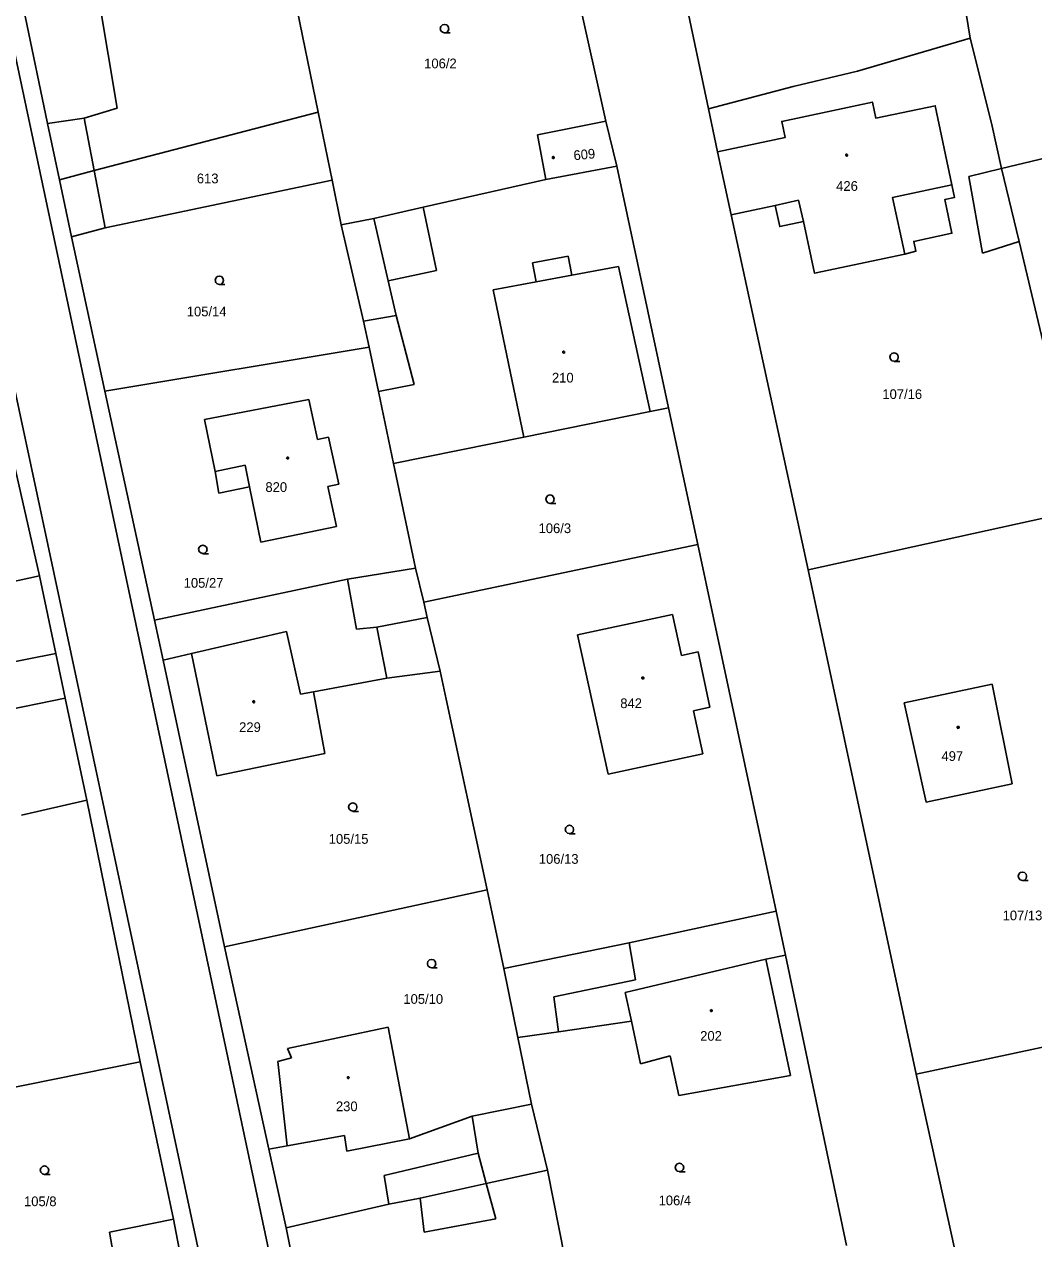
# Model space of a CAD drawing. Extents: x -757994 to -755874, y -1047691 to -1046119.
# Drawn here: x -756698 to -756609.7, y -1047019.3 to -1046913.1 of the extents above; entities that cross this region are included whole.
import ezdxf

# ---------------------------------------------------------------- set-up
doc = ezdxf.new("R2010")
doc.units = 0
doc.layers.add('katastrální mapa', color=7, linetype='Continuous')

msp = doc.modelspace()

# ---------------------------------------------------------------- linework, layer by layer
at = {"layer": 'katastrální mapa'}
for p, q in [((-756646.95, -1046878.79), (-756638.18, -1046920.5)), ((-756653.57, -1046892.67), (-756647.16, -1046921.56)), ((-756701.95, -1046901.14), (-756668.39, -1047059.3)), ((-756707.71, -1046903.74), (-756665.23, -1047102.74)), ((-756675.68, -1046904.52), (-756672.34, -1046920.77)), ((-756689.92, -1046920.42), (-756691.5, -1046911.04)), ((-756615.84, -1046910.85), (-756615.3, -1046914.3)), ((-756697.97, -1046912.37), (-756696.02, -1046921.77)), ((-756615.3, -1046914.3), (-756625.14, -1046917.2)), ((-756613.43, -1046921.73), (-756615.3, -1046914.3)), ((-756625.14, -1046917.2), (-756630.78, -1046918.54)), ((-756630.78, -1046918.54), (-756638.18, -1046920.5)), ((-756692.82, -1046921.29), (-756689.92, -1046920.42)), ((-756691.94, -1046925.89), (-756672.34, -1046920.77)), ((-756672.34, -1046920.77), (-756671.12, -1046926.73)), ((-756638.18, -1046920.5), (-756637.39, -1046924.25)), ((-756591.53, -1046920.69), (-756612.56, -1046925.71)), ((-756692.82, -1046921.29), (-756696.02, -1046921.77)), ((-756696.02, -1046921.77), (-756694.97, -1046926.69)), ((-756691.94, -1046925.89), (-756692.82, -1046921.29)), ((-756647.16, -1046921.56), (-756653.13, -1046922.75)), ((-756647.16, -1046921.56), (-756646.2, -1046925.51)), ((-756612.56, -1046925.71), (-756613.43, -1046921.73)), ((-756653.13, -1046922.75), (-756652.41, -1046926.68)), ((-756637.39, -1046924.25), (-756637.02, -1046926)), ((-756694.97, -1046926.69), (-756691.94, -1046925.89)), ((-756690.98, -1046930.9), (-756691.94, -1046925.89)), ((-756652.41, -1046926.68), (-756646.2, -1046925.51)), ((-756646.2, -1046925.51), (-756641.68, -1046946.63)), ((-756637.02, -1046926), (-756636.2, -1046929.77)), ((-756612.56, -1046925.71), (-756615.4, -1046926.4)), ((-756612.56, -1046925.71), (-756610.99, -1046932.1)), ((-756694.97, -1046926.69), (-756693.91, -1046931.68)), ((-756671.12, -1046926.73), (-756690.98, -1046930.9)), ((-756671.12, -1046926.73), (-756670.32, -1046930.62)), ((-756663.16, -1046929.1), (-756652.41, -1046926.68)), ((-756615.4, -1046926.4), (-756614.2, -1046933.1)), ((-756667.45, -1046930.07), (-756663.16, -1046929.1)), ((-756661.99, -1046934.64), (-756663.16, -1046929.1)), ((-756632.35, -1046928.95), (-756636.2, -1046929.77)), ((-756670.32, -1046930.62), (-756667.45, -1046930.07)), ((-756667.45, -1046930.07), (-756666.2, -1046935.54)), ((-756636.2, -1046929.77), (-756629.47, -1046960.81)), ((-756690.98, -1046930.9), (-756693.91, -1046931.68)), ((-756668.36, -1046939.07), (-756670.32, -1046930.62)), ((-756693.91, -1046931.68), (-756690.99, -1046945.19)), ((-756614.2, -1046933.1), (-756610.99, -1046932.1)), ((-756610.99, -1046932.1), (-756607.95, -1046944.99)), ((-756653.58, -1046933.96), (-756650.45, -1046933.38)), ((-756650.45, -1046933.38), (-756650.14, -1046935.05)), ((-756666.2, -1046935.54), (-756661.99, -1046934.64)), ((-756653.27, -1046935.63), (-756653.58, -1046933.96)), ((-756646.06, -1046934.29), (-756650.14, -1046935.05)), ((-756643.29, -1046946.96), (-756646.06, -1046934.29)), ((-756666.2, -1046935.54), (-756665.5, -1046938.56)), ((-756653.27, -1046935.63), (-756657.01, -1046936.33)), ((-756650.14, -1046935.05), (-756653.27, -1046935.63)), ((-756657.01, -1046936.33), (-756654.33, -1046949.2)), ((-756668.36, -1046939.07), (-756665.5, -1046938.56)), ((-756667.88, -1046941.33), (-756668.36, -1046939.07)), ((-756665.5, -1046938.56), (-756663.94, -1046944.59)), ((-756690.99, -1046945.19), (-756667.88, -1046941.33)), ((-756667.06, -1046945.2), (-756667.88, -1046941.33)), ((-756690.99, -1046945.19), (-756686.65, -1046965.22)), ((-756663.94, -1046944.59), (-756667.06, -1046945.2)), ((-756665.73, -1046951.51), (-756667.06, -1046945.2)), ((-756682.27, -1046947.66), (-756673.15, -1046945.91)), ((-756673.15, -1046945.91), (-756672.39, -1046949.41)), ((-756643.29, -1046946.96), (-756654.33, -1046949.2)), ((-756641.68, -1046946.63), (-756643.29, -1046946.96)), ((-756641.68, -1046946.63), (-756639.12, -1046958.59)), ((-756681.34, -1046952.21), (-756682.27, -1046947.66)), ((-756672.39, -1046949.41), (-756671.42, -1046949.2)), ((-756671.42, -1046949.2), (-756670.52, -1046953.32)), ((-756654.33, -1046949.2), (-756665.73, -1046951.51)), ((-756699.34, -1046949.77), (-756696.71, -1046961.35)), ((-756678.71, -1046951.67), (-756681.34, -1046952.21)), ((-756678.33, -1046953.54), (-756678.71, -1046951.67)), ((-756665.73, -1046951.51), (-756663.81, -1046960.66)), ((-756681.03, -1046954.1), (-756681.34, -1046952.21)), ((-756678.33, -1046953.54), (-756681.03, -1046954.1)), ((-756677.34, -1046958.38), (-756678.33, -1046953.54)), ((-756670.52, -1046953.32), (-756671.49, -1046953.53)), ((-756671.49, -1046953.53), (-756670.72, -1046957.03)), ((-756605.91, -1046955.64), (-756629.47, -1046960.81)), ((-756670.72, -1046957.03), (-756677.34, -1046958.38)), ((-756663.1, -1046963.65), (-756639.12, -1046958.59)), ((-756639.12, -1046958.59), (-756632.25, -1046990.67)), ((-756703.57, -1046962.84), (-756696.71, -1046961.35)), ((-756696.71, -1046961.35), (-756695.28, -1046968.13)), ((-756663.81, -1046960.66), (-756669.76, -1046961.62)), ((-756663.1, -1046963.65), (-756663.81, -1046960.66)), ((-756629.47, -1046960.81), (-756620, -1047004.93)), ((-756669.76, -1046961.62), (-756686.65, -1046965.22)), ((-756668.99, -1046965.99), (-756669.76, -1046961.62)), ((-756662.79, -1046964.97), (-756663.1, -1046963.65)), ((-756686.65, -1046965.22), (-756685.9, -1046968.71)), ((-756662.79, -1046964.97), (-756667.21, -1046965.82)), ((-756661.65, -1046969.69), (-756662.79, -1046964.97)), ((-756649.65, -1046966.51), (-756641.32, -1046964.73)), ((-756641.32, -1046964.73), (-756640.55, -1046968.31)), ((-756675.1, -1046966.22), (-756683.43, -1046968.14)), ((-756673.87, -1046971.7), (-756675.1, -1046966.22)), ((-756667.21, -1046965.82), (-756668.99, -1046965.99)), ((-756667.21, -1046965.82), (-756666.34, -1046970.29)), ((-756646.95, -1046978.68), (-756649.65, -1046966.51)), ((-756695.28, -1046968.13), (-756702.22, -1046969.5)), ((-756695.28, -1046968.13), (-756694.46, -1046972.05)), ((-756683.43, -1046968.14), (-756685.9, -1046968.71)), ((-756685.9, -1046968.71), (-756680.53, -1046993.8)), ((-756681.2, -1046978.82), (-756683.43, -1046968.14)), ((-756640.55, -1046968.31), (-756639.09, -1046967.99)), ((-756639.09, -1046967.99), (-756638.06, -1046972.83)), ((-756661.65, -1046969.69), (-756666.34, -1046970.29)), ((-756661.13, -1046972.14), (-756661.65, -1046969.69)), ((-756666.34, -1046970.29), (-756672.73, -1046971.49)), ((-756621.07, -1046972.45), (-756613.35, -1046970.82)), ((-756613.35, -1046970.82), (-756611.61, -1046979.54)), ((-756672.73, -1046971.49), (-756673.87, -1046971.7)), ((-756672.73, -1046971.49), (-756671.74, -1046976.88)), ((-756704.07, -1046974), (-756694.46, -1046972.05)), ((-756694.46, -1046972.05), (-756692.58, -1046980.95)), ((-756657.55, -1046988.82), (-756661.13, -1046972.14)), ((-756638.06, -1046972.83), (-756639.5, -1046973.14)), ((-756619.13, -1046981.15), (-756621.07, -1046972.45)), ((-756639.5, -1046973.14), (-756638.67, -1046976.9)), ((-756671.74, -1046976.88), (-756681.2, -1046978.82)), ((-756638.67, -1046976.9), (-756646.95, -1046978.68)), ((-756611.61, -1046979.54), (-756619.13, -1046981.15)), ((-756698.29, -1046982.28), (-756692.58, -1046980.95)), ((-756692.58, -1046980.95), (-756687.9, -1047003.85)), ((-756657.55, -1046988.82), (-756680.53, -1046993.8)), ((-756656.09, -1046995.68), (-756657.55, -1046988.82)), ((-756632.25, -1046990.67), (-756645.13, -1046993.44)), ((-756632.25, -1046990.67), (-756631.44, -1046994.52)), ((-756680.53, -1046993.8), (-756676.64, -1047011.49)), ((-756645.13, -1046993.44), (-756656.09, -1046995.68)), ((-756644.57, -1046996.67), (-756645.13, -1046993.44)), ((-756633.18, -1046994.87), (-756645.47, -1046997.78)), ((-756633.18, -1046994.87), (-756631.44, -1046994.52)), ((-756631.01, -1047005.06), (-756633.18, -1046994.87)), ((-756631.44, -1046994.52), (-756626.1, -1047019.92)), ((-756656.09, -1046995.68), (-756654.86, -1047001.73)), ((-756651.71, -1046998.16), (-756644.57, -1046996.67)), ((-756651.3, -1047001.22), (-756651.71, -1046998.16)), ((-756645.47, -1046997.78), (-756644.92, -1047000.31)), ((-756651.3, -1047001.22), (-756644.92, -1047000.31)), ((-756644.92, -1047000.31), (-756644.12, -1047004.02)), ((-756596.57, -1046999.9), (-756620, -1047004.93)), ((-756666.2, -1047000.81), (-756675.02, -1047002.69)), ((-756664.35, -1047010.59), (-756666.2, -1047000.81)), ((-756654.86, -1047001.73), (-756651.3, -1047001.22)), ((-756654.86, -1047001.73), (-756653.66, -1047007.56)), ((-756675.02, -1047002.69), (-756674.68, -1047003.5)), ((-756709.03, -1047008.1), (-756687.9, -1047003.85)), ((-756687.9, -1047003.85), (-756685, -1047017.62)), ((-756674.68, -1047003.5), (-756675.85, -1047003.82)), ((-756675.85, -1047003.82), (-756675.06, -1047011.21)), ((-756644.12, -1047004.02), (-756641.54, -1047003.33)), ((-756641.54, -1047003.33), (-756640.79, -1047006.79)), ((-756620, -1047004.93), (-756610.71, -1047047.28)), ((-756640.79, -1047006.79), (-756631.01, -1047005.06)), ((-756653.66, -1047007.56), (-756658.85, -1047008.62)), ((-756653.66, -1047007.56), (-756652.26, -1047013.32)), ((-756658.85, -1047008.62), (-756664.35, -1047010.59)), ((-756658.85, -1047008.62), (-756658.34, -1047011.83)), ((-756675.06, -1047011.21), (-756676.64, -1047011.49)), ((-756670.03, -1047010.31), (-756675.06, -1047011.21)), ((-756669.83, -1047011.68), (-756670.03, -1047010.31)), ((-756664.35, -1047010.59), (-756669.83, -1047011.68)), ((-756676.64, -1047011.49), (-756675.13, -1047018.38)), ((-756658.34, -1047011.83), (-756666.56, -1047013.81)), ((-756658.34, -1047011.83), (-756657.65, -1047014.49)), ((-756652.26, -1047013.32), (-756657.65, -1047014.49)), ((-756652.26, -1047013.32), (-756650.75, -1047021)), ((-756666.56, -1047013.81), (-756666.15, -1047016.3)), ((-756657.65, -1047014.49), (-756663.41, -1047015.78)), ((-756656.78, -1047017.6), (-756657.65, -1047014.49)), ((-756666.15, -1047016.3), (-756675.13, -1047018.38)), ((-756663.41, -1047015.78), (-756666.15, -1047016.3)), ((-756663.41, -1047015.78), (-756663.05, -1047018.75)), ((-756690.59, -1047018.75), (-756685, -1047017.62)), ((-756685, -1047017.62), (-756684.26, -1047021.44)), ((-756663.05, -1047018.75), (-756656.78, -1047017.6)), ((-756689.9, -1047022.72), (-756690.59, -1047018.75)), ((-756675.13, -1047018.38), (-756673.7, -1047025.49))]:
    msp.add_line(p, q, dxfattribs=at)
for points in [[(-756661.27, -1046913.84), (-756661.46, -1046913.79), (-756661.6, -1046913.66), (-756661.65, -1046913.47), (-756661.6, -1046913.28), (-756661.46, -1046913.15), (-756661.28, -1046913.1), (-756661.09, -1046913.15), (-756660.96, -1046913.28), (-756660.91, -1046913.48), (-756660.96, -1046913.67), (-756661.09, -1046913.8), (-756661.28, -1046913.85), (-756660.78, -1046913.85)], [(-756637.39, -1046924.25), (-756631.48, -1046923), (-756631.78, -1046921.59), (-756623.84, -1046919.9), (-756623.55, -1046921.3), (-756618.35, -1046920.21), (-756616.9, -1046927.12)], [(-756621.01, -1046933.19), (-756622.08, -1046928.24), (-756616.9, -1046927.12)], [(-756616.9, -1046927.12), (-756616.67, -1046928.25), (-756617.51, -1046928.43), (-756616.89, -1046931.37), (-756620.22, -1046932.08), (-756620.04, -1046932.95), (-756621.01, -1046933.19)], [(-756632.35, -1046928.95), (-756630.31, -1046928.48), (-756629.87, -1046930.34)], [(-756629.87, -1046930.34), (-756631.95, -1046930.79), (-756632.35, -1046928.95)], [(-756621.01, -1046933.19), (-756628.9, -1046934.87), (-756629.87, -1046930.34)], [(-756680.98, -1046935.85), (-756681.17, -1046935.8), (-756681.3, -1046935.67), (-756681.35, -1046935.48), (-756681.3, -1046935.29), (-756681.17, -1046935.16), (-756680.98, -1046935.11), (-756680.8, -1046935.16), (-756680.67, -1046935.29), (-756680.61, -1046935.49), (-756680.67, -1046935.68), (-756680.8, -1046935.81), (-756680.99, -1046935.86), (-756680.49, -1046935.86)], [(-756621.94, -1046942.57), (-756622.13, -1046942.52), (-756622.26, -1046942.39), (-756622.32, -1046942.2), (-756622.26, -1046942.01), (-756622.13, -1046941.88), (-756621.95, -1046941.83), (-756621.76, -1046941.88), (-756621.62, -1046942.01), (-756621.58, -1046942.21), (-756621.62, -1046942.4), (-756621.76, -1046942.53), (-756621.95, -1046942.58), (-756621.45, -1046942.58)], [(-756652.04, -1046955), (-756652.23, -1046954.95), (-756652.36, -1046954.82), (-756652.42, -1046954.63), (-756652.36, -1046954.45), (-756652.23, -1046954.31), (-756652.05, -1046954.26), (-756651.86, -1046954.31), (-756651.73, -1046954.45), (-756651.68, -1046954.64), (-756651.73, -1046954.83), (-756651.86, -1046954.96), (-756652.05, -1046955.01), (-756651.55, -1046955.01)], [(-756682.42, -1046959.39), (-756682.61, -1046959.34), (-756682.75, -1046959.21), (-756682.8, -1046959.02), (-756682.75, -1046958.84), (-756682.61, -1046958.7), (-756682.43, -1046958.65), (-756682.24, -1046958.7), (-756682.1, -1046958.84), (-756682.06, -1046959.03), (-756682.1, -1046959.22), (-756682.24, -1046959.35), (-756682.43, -1046959.4), (-756681.93, -1046959.4)], [(-756669.3, -1046981.93), (-756669.49, -1046981.88), (-756669.62, -1046981.75), (-756669.68, -1046981.56), (-756669.62, -1046981.38), (-756669.49, -1046981.24), (-756669.31, -1046981.19), (-756669.12, -1046981.24), (-756668.99, -1046981.38), (-756668.94, -1046981.57), (-756668.99, -1046981.76), (-756669.12, -1046981.89), (-756669.31, -1046981.94), (-756668.81, -1046981.94)], [(-756650.34, -1046983.89), (-756650.53, -1046983.84), (-756650.67, -1046983.71), (-756650.72, -1046983.52), (-756650.67, -1046983.34), (-756650.53, -1046983.2), (-756650.35, -1046983.15), (-756650.16, -1046983.2), (-756650.02, -1046983.34), (-756649.98, -1046983.53), (-756650.02, -1046983.72), (-756650.16, -1046983.85), (-756650.35, -1046983.9), (-756649.85, -1046983.9)], [(-756610.71, -1046987.99), (-756610.9, -1046987.94), (-756611.03, -1046987.8), (-756611.09, -1046987.62), (-756611.03, -1046987.44), (-756610.9, -1046987.3), (-756610.72, -1046987.25), (-756610.53, -1046987.3), (-756610.4, -1046987.44), (-756610.35, -1046987.62), (-756610.4, -1046987.82), (-756610.53, -1046987.95), (-756610.72, -1046988), (-756610.22, -1046988)], [(-756662.4, -1046995.63), (-756662.59, -1046995.58), (-756662.73, -1046995.45), (-756662.78, -1046995.26), (-756662.73, -1046995.08), (-756662.59, -1046994.94), (-756662.41, -1046994.89), (-756662.22, -1046994.94), (-756662.09, -1046995.08), (-756662.04, -1046995.27), (-756662.09, -1046995.46), (-756662.22, -1046995.59), (-756662.41, -1046995.64), (-756661.91, -1046995.64)], [(-756696.27, -1047013.7), (-756696.46, -1047013.65), (-756696.6, -1047013.51), (-756696.65, -1047013.33), (-756696.6, -1047013.15), (-756696.46, -1047013.01), (-756696.28, -1047012.96), (-756696.09, -1047013.01), (-756695.96, -1047013.15), (-756695.91, -1047013.34), (-756695.96, -1047013.52), (-756696.09, -1047013.66), (-756696.28, -1047013.71), (-756695.78, -1047013.71)], [(-756640.72, -1047013.46), (-756640.91, -1047013.41), (-756641.04, -1047013.27), (-756641.1, -1047013.09), (-756641.04, -1047012.91), (-756640.91, -1047012.77), (-756640.73, -1047012.72), (-756640.54, -1047012.77), (-756640.41, -1047012.91), (-756640.35, -1047013.1), (-756640.41, -1047013.28), (-756640.54, -1047013.42), (-756640.73, -1047013.47), (-756640.23, -1047013.47)]]:
    msp.add_lwpolyline(points, dxfattribs=at)
for points in [[(-756651.76, -1046924.67), (-756651.71, -1046924.68), (-756651.69, -1046924.72), (-756651.68, -1046924.75), (-756651.69, -1046924.79), (-756651.73, -1046924.83), (-756651.76, -1046924.84), (-756651.8, -1046924.82), (-756651.84, -1046924.79), (-756651.85, -1046924.75), (-756651.84, -1046924.71), (-756651.79, -1046924.67)], [(-756626.1, -1046924.46), (-756626.05, -1046924.47), (-756626.02, -1046924.51), (-756626.01, -1046924.54), (-756626.02, -1046924.59), (-756626.07, -1046924.62), (-756626.1, -1046924.62), (-756626.15, -1046924.61), (-756626.18, -1046924.58), (-756626.19, -1046924.54), (-756626.18, -1046924.5), (-756626.14, -1046924.46)], [(-756650.85, -1046941.69), (-756650.8, -1046941.7), (-756650.77, -1046941.74), (-756650.76, -1046941.77), (-756650.77, -1046941.82), (-756650.82, -1046941.85), (-756650.85, -1046941.86), (-756650.9, -1046941.84), (-756650.93, -1046941.81), (-756650.94, -1046941.77), (-756650.93, -1046941.73), (-756650.89, -1046941.69)], [(-756675.01, -1046950.95), (-756674.96, -1046950.96), (-756674.94, -1046951), (-756674.93, -1046951.03), (-756674.94, -1046951.08), (-756674.98, -1046951.11), (-756675.01, -1046951.12), (-756675.05, -1046951.1), (-756675.09, -1046951.07), (-756675.1, -1046951.03), (-756675.09, -1046950.99), (-756675.04, -1046950.95)], [(-756643.93, -1046970.19), (-756643.88, -1046970.2), (-756643.85, -1046970.24), (-756643.85, -1046970.27), (-756643.85, -1046970.32), (-756643.9, -1046970.35), (-756643.93, -1046970.36), (-756643.98, -1046970.34), (-756644.01, -1046970.31), (-756644.02, -1046970.27), (-756644.01, -1046970.23), (-756643.97, -1046970.19)], [(-756677.98, -1046972.27), (-756677.93, -1046972.28), (-756677.91, -1046972.33), (-756677.9, -1046972.36), (-756677.91, -1046972.41), (-756677.95, -1046972.44), (-756677.98, -1046972.45), (-756678.02, -1046972.43), (-756678.05, -1046972.4), (-756678.07, -1046972.36), (-756678.05, -1046972.32), (-756678.01, -1046972.28)], [(-756616.34, -1046974.5), (-756616.29, -1046974.51), (-756616.26, -1046974.56), (-756616.25, -1046974.59), (-756616.26, -1046974.64), (-756616.3, -1046974.67), (-756616.34, -1046974.68), (-756616.39, -1046974.66), (-756616.42, -1046974.63), (-756616.43, -1046974.59), (-756616.42, -1046974.54), (-756616.38, -1046974.51)], [(-756637.94, -1046999.28), (-756637.89, -1046999.29), (-756637.86, -1046999.34), (-756637.85, -1046999.37), (-756637.86, -1046999.42), (-756637.91, -1046999.45), (-756637.94, -1046999.46), (-756637.98, -1046999.44), (-756638.01, -1046999.41), (-756638.02, -1046999.37), (-756638.01, -1046999.33), (-756637.97, -1046999.29)], [(-756669.71, -1047005.16), (-756669.66, -1047005.17), (-756669.64, -1047005.21), (-756669.62, -1047005.24), (-756669.64, -1047005.28), (-756669.68, -1047005.32), (-756669.71, -1047005.33), (-756669.75, -1047005.31), (-756669.78, -1047005.28), (-756669.79, -1047005.24), (-756669.78, -1047005.2), (-756669.74, -1047005.16)]]:
    msp.add_lwpolyline(points, close=True, dxfattribs=at)

# ---------------------------------------------------------------- texts
for s, p in [('106/2', (-756663.06, -1046916.94)), ('613', (-756682.95, -1046927)), ('426', (-756627.01, -1046927.66)), ('105/14', (-756683.83, -1046938.64)), ('210', (-756651.88, -1046944.43)), ('107/16', (-756622.97, -1046945.87)), ('820', (-756676.95, -1046954)), ('106/3', (-756653.05, -1046957.6)), ('105/27', (-756684.1, -1046962.38)), ('842', (-756645.9, -1046972.91)), ('229', (-756679.25, -1046975)), ('497', (-756617.8, -1046977.53)), ('105/15', (-756671.41, -1046984.78)), ('106/13', (-756653.03, -1046986.53)), ('107/13', (-756612.45, -1046991.47)), ('105/10', (-756664.88, -1046998.78)), ('202', (-756638.91, -1047002.01)), ('230', (-756670.78, -1047008.17)), ('105/8', (-756698.07, -1047016.48)), ('106/4', (-756642.55, -1047016.4))]:
    msp.add_text(s, height=0.85, dxfattribs=at).set_placement(p)
msp.add_text('609', height=0.85, rotation=5.5577, dxfattribs=at).set_placement((-756649.95, -1046924.99))

doc.saveas('drawing.dxf')
